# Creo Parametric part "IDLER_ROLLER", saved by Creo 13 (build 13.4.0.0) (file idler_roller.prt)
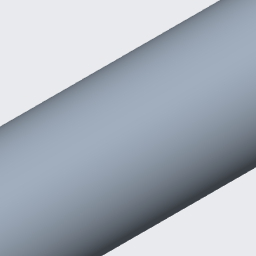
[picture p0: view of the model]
Units: millimeter Newton Second (mmNs); MM, TONNE, SECS

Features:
  1. datum plane "RIGHT"
  2. datum plane "TOP"
  3. datum plane "FRONT"
  4. coordinate system
  5. protrusion
  6. protrusion
  7. protrusion

Surfaces: 4 plane, 3 cylinder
